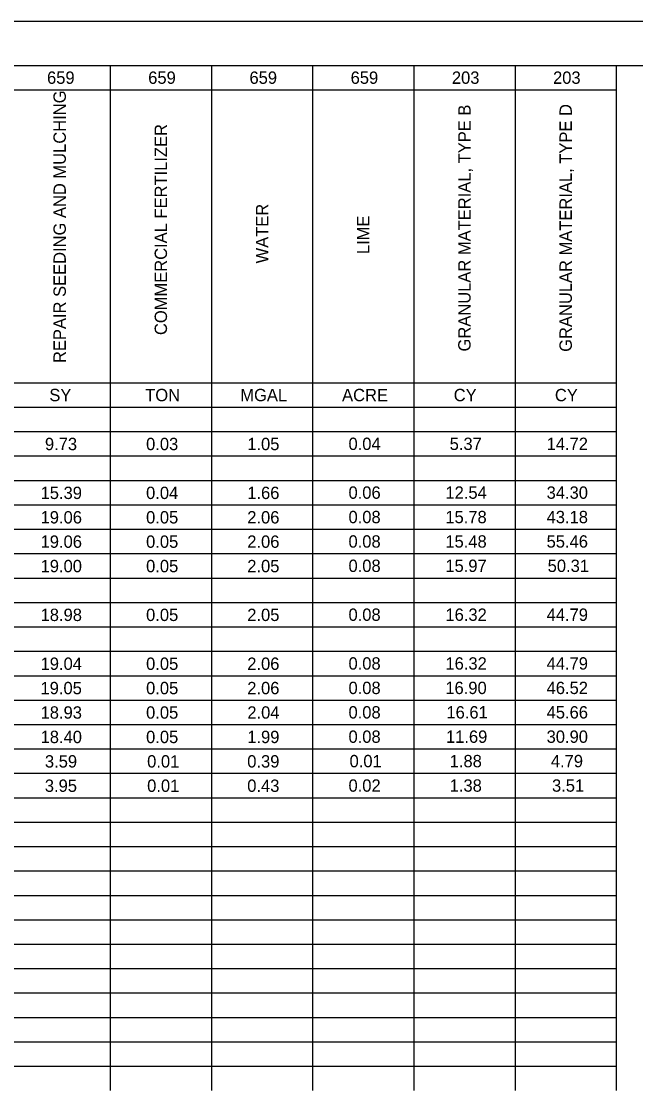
# Model space of a CAD drawing. Extents: x 0 to 34, y 0 to 22.
# Drawn here: x 19.1 to 26.06, y 9.88 to 22 of the extents above; entities that cross this region are included whole.
import ezdxf

# ---------------------------------------------------------------- set-up
doc = ezdxf.new("R2010")
doc.units = 0
for name, color, linetype in [('Default', 7, 'Continuous'), ('SH_Border', 7, 'Continuous'), ('SH_Cut_Line', 7, 'Continuous')]:
    doc.layers.add(name, color=color, linetype=linetype)

msp = doc.modelspace()

# ---------------------------------------------------------------- linework, layer by layer
at = {"layer": 'Default'}
for p, q in [((15.52, 21.5), (25.837, 21.5)), ((20.105, 21.5), (20.105, 21.223)), ((21.252, 21.5), (21.252, 21.223)), ((22.398, 21.5), (22.398, 21.223)), ((23.544, 21.5), (23.544, 21.223)), ((24.691, 21.5), (24.691, 21.223)), ((25.837, 21.5), (25.837, 21.223)), ((15.52, 21.223), (25.837, 21.223)), ((20.105, 21.223), (20.105, 20.947)), ((21.252, 21.223), (21.252, 20.947)), ((22.398, 21.223), (22.398, 20.947)), ((23.544, 21.223), (23.544, 20.947)), ((24.691, 21.223), (24.691, 20.947)), ((25.837, 21.223), (25.837, 20.947)), ((20.105, 20.947), (20.105, 20.67)), ((21.252, 20.947), (21.252, 20.67)), ((22.398, 20.947), (22.398, 20.67)), ((23.544, 20.947), (23.544, 20.67)), ((24.691, 20.947), (24.691, 20.67)), ((25.837, 20.947), (25.837, 20.67)), ((20.105, 20.67), (20.105, 20.116)), ((21.252, 20.67), (21.252, 20.116)), ((22.398, 20.67), (22.398, 20.116)), ((23.544, 20.67), (23.544, 20.116)), ((24.691, 20.67), (24.691, 20.116)), ((25.837, 20.67), (25.837, 20.116)), ((20.105, 20.116), (20.105, 19.84)), ((21.252, 20.116), (21.252, 19.84)), ((22.398, 20.116), (22.398, 19.84)), ((23.544, 20.116), (23.544, 19.84)), ((24.691, 20.116), (24.691, 19.84)), ((25.837, 20.116), (25.837, 19.84)), ((20.105, 19.84), (20.105, 19.563)), ((21.252, 19.84), (21.252, 19.563)), ((22.398, 19.84), (22.398, 19.563)), ((23.544, 19.84), (23.544, 19.563)), ((24.691, 19.84), (24.691, 19.563)), ((25.837, 19.84), (25.837, 19.563)), ((20.105, 19.563), (20.105, 19.286)), ((21.252, 19.563), (21.252, 19.286)), ((22.398, 19.563), (22.398, 19.286)), ((23.544, 19.563), (23.544, 19.286)), ((24.691, 19.563), (24.691, 19.286)), ((25.837, 19.563), (25.837, 19.286)), ((20.105, 19.286), (20.105, 19.01)), ((21.252, 19.286), (21.252, 19.01)), ((22.398, 19.286), (22.398, 19.01)), ((23.544, 19.286), (23.544, 19.01)), ((24.691, 19.286), (24.691, 19.01)), ((25.837, 19.286), (25.837, 19.01)), ((20.105, 19.01), (20.105, 18.733)), ((21.252, 19.01), (21.252, 18.733)), ((22.398, 19.01), (22.398, 18.733)), ((23.544, 19.01), (23.544, 18.733)), ((24.691, 19.01), (24.691, 18.733)), ((25.837, 19.01), (25.837, 18.733)), ((20.105, 18.733), (20.105, 18.456)), ((21.252, 18.733), (21.252, 18.456)), ((22.398, 18.733), (22.398, 18.456)), ((23.544, 18.733), (23.544, 18.456)), ((24.691, 18.733), (24.691, 18.456)), ((25.837, 18.733), (25.837, 18.456)), ((20.105, 18.456), (20.105, 18.18)), ((21.252, 18.456), (21.252, 18.18)), ((22.398, 18.456), (22.398, 18.18)), ((23.544, 18.456), (23.544, 18.18)), ((24.691, 18.456), (24.691, 18.18)), ((25.837, 18.456), (25.837, 18.18)), ((20.105, 18.18), (20.105, 17.903)), ((21.252, 18.18), (21.252, 17.903)), ((22.398, 18.18), (22.398, 17.903)), ((23.544, 18.18), (23.544, 17.903)), ((24.691, 18.18), (24.691, 17.903)), ((25.837, 18.18), (25.837, 17.903)), ((15.52, 17.903), (25.837, 17.903)), ((20.105, 17.903), (20.105, 17.626)), ((21.252, 17.903), (21.252, 17.626)), ((22.398, 17.903), (22.398, 17.626)), ((23.544, 17.903), (23.544, 17.626)), ((24.691, 17.903), (24.691, 17.626)), ((25.837, 17.903), (25.837, 17.626)), ((15.52, 17.626), (25.837, 17.626)), ((20.105, 17.626), (20.105, 17.349)), ((21.252, 17.626), (21.252, 17.349)), ((22.398, 17.626), (22.398, 17.349)), ((23.544, 17.626), (23.544, 17.349)), ((24.691, 17.626), (24.691, 17.349)), ((25.837, 17.626), (25.837, 17.349)), ((15.52, 17.349), (25.837, 17.349)), ((20.105, 17.349), (20.105, 17.073)), ((21.252, 17.349), (21.252, 17.073)), ((22.398, 17.349), (22.398, 17.073)), ((23.544, 17.349), (23.544, 17.073)), ((24.691, 17.349), (24.691, 17.073)), ((25.837, 17.349), (25.837, 17.073)), ((15.52, 17.073), (25.837, 17.073)), ((20.105, 17.073), (20.105, 16.796)), ((21.252, 17.073), (21.252, 16.796)), ((22.398, 17.073), (22.398, 16.796)), ((23.544, 17.073), (23.544, 16.796)), ((24.691, 17.073), (24.691, 16.796)), ((25.837, 17.073), (25.837, 16.796)), ((15.52, 16.796), (25.837, 16.796)), ((20.105, 16.796), (20.105, 16.243)), ((21.252, 16.796), (21.252, 16.243)), ((22.398, 16.796), (22.398, 16.243)), ((23.544, 16.796), (23.544, 16.243)), ((24.691, 16.796), (24.691, 16.243)), ((25.837, 16.796), (25.837, 16.243)), ((15.52, 16.519), (25.837, 16.519)), ((15.52, 16.243), (25.837, 16.243)), ((20.105, 16.243), (20.105, 15.966)), ((21.252, 16.243), (21.252, 15.966)), ((22.398, 16.243), (22.398, 15.966)), ((23.544, 16.243), (23.544, 15.966)), ((24.691, 16.243), (24.691, 15.966)), ((25.837, 16.243), (25.837, 15.966)), ((15.52, 15.966), (25.837, 15.966)), ((20.105, 15.966), (20.105, 15.689)), ((21.252, 15.966), (21.252, 15.689)), ((22.398, 15.966), (22.398, 15.689)), ((23.544, 15.966), (23.544, 15.689)), ((24.691, 15.966), (24.691, 15.689)), ((25.837, 15.966), (25.837, 15.689)), ((15.52, 15.689), (25.837, 15.689)), ((20.105, 15.689), (20.105, 15.412)), ((21.252, 15.689), (21.252, 15.412)), ((22.398, 15.689), (22.398, 15.412)), ((23.544, 15.689), (23.544, 15.412)), ((24.691, 15.689), (24.691, 15.412)), ((25.837, 15.689), (25.837, 15.412)), ((15.52, 15.412), (25.837, 15.412)), ((20.105, 15.412), (20.105, 14.859)), ((21.252, 15.412), (21.252, 14.859)), ((22.398, 15.412), (22.398, 14.859)), ((23.544, 15.412), (23.544, 14.859)), ((24.691, 15.412), (24.691, 14.859)), ((25.837, 15.412), (25.837, 14.859)), ((15.52, 15.136), (25.837, 15.136)), ((15.52, 14.859), (25.837, 14.859)), ((20.105, 14.859), (20.105, 14.582)), ((21.252, 14.859), (21.252, 14.582)), ((22.398, 14.859), (22.398, 14.582)), ((23.544, 14.859), (23.544, 14.582)), ((24.691, 14.859), (24.691, 14.582)), ((25.837, 14.859), (25.837, 14.582)), ((15.52, 14.582), (25.837, 14.582)), ((20.105, 14.582), (20.105, 14.306)), ((21.252, 14.582), (21.252, 14.306)), ((22.398, 14.582), (22.398, 14.306)), ((23.544, 14.582), (23.544, 14.306)), ((24.691, 14.582), (24.691, 14.306)), ((25.837, 14.582), (25.837, 14.306)), ((15.52, 14.306), (25.837, 14.306)), ((20.105, 14.306), (20.105, 14.029)), ((21.252, 14.306), (21.252, 14.029)), ((22.398, 14.306), (22.398, 14.029)), ((23.544, 14.306), (23.544, 14.029)), ((24.691, 14.306), (24.691, 14.029)), ((25.837, 14.306), (25.837, 14.029)), ((15.52, 14.029), (25.837, 14.029)), ((20.105, 14.029), (20.105, 13.199)), ((21.252, 14.029), (21.252, 13.199)), ((22.398, 14.029), (22.398, 13.199)), ((23.544, 14.029), (23.544, 13.199)), ((24.691, 14.029), (24.691, 13.199)), ((25.837, 14.029), (25.837, 13.199)), ((15.52, 13.752), (25.837, 13.752)), ((15.52, 13.476), (25.837, 13.476)), ((15.52, 13.199), (25.837, 13.199)), ((20.105, 13.199), (20.105, 12.922)), ((21.252, 13.199), (21.252, 12.922)), ((22.398, 13.199), (22.398, 12.922)), ((23.544, 13.199), (23.544, 12.922)), ((24.691, 13.199), (24.691, 12.922)), ((25.837, 13.199), (25.837, 12.922)), ((15.52, 12.922), (25.837, 12.922)), ((20.105, 12.922), (20.105, 11.815)), ((21.252, 12.922), (21.252, 11.815)), ((22.398, 12.922), (22.398, 11.815)), ((23.544, 12.922), (23.544, 11.815)), ((24.691, 12.922), (24.691, 11.815)), ((25.837, 12.922), (25.837, 11.815)), ((15.52, 12.645), (25.837, 12.645)), ((15.52, 12.369), (25.837, 12.369)), ((15.52, 12.092), (25.837, 12.092)), ((15.52, 11.815), (25.837, 11.815)), ((20.105, 11.815), (20.105, 11.539)), ((21.252, 11.815), (21.252, 11.539)), ((22.398, 11.815), (22.398, 11.539)), ((23.544, 11.815), (23.544, 11.539)), ((24.691, 11.815), (24.691, 11.539)), ((25.837, 11.815), (25.837, 11.539)), ((15.52, 11.539), (25.837, 11.539)), ((20.105, 11.539), (20.105, 10.432)), ((21.252, 11.539), (21.252, 10.432)), ((22.398, 11.539), (22.398, 10.432)), ((23.544, 11.539), (23.544, 10.432)), ((24.691, 11.539), (24.691, 10.432)), ((25.837, 11.539), (25.837, 10.432)), ((15.52, 11.262), (25.837, 11.262)), ((15.52, 10.985), (25.837, 10.985)), ((15.52, 10.708), (25.837, 10.708)), ((15.52, 10.432), (25.837, 10.432)), ((20.105, 10.432), (20.105, 9.878)), ((21.252, 10.432), (21.252, 9.878)), ((22.398, 10.432), (22.398, 9.878)), ((23.544, 10.432), (23.544, 9.878)), ((24.691, 10.432), (24.691, 9.878)), ((25.837, 10.432), (25.837, 9.878)), ((15.52, 10.155), (25.837, 10.155))]:
    msp.add_line(p, q, dxfattribs=at)
at = {"layer": 'SH_Border'}
msp.add_lwpolyline([(1.5, 21.5), (33.5, 21.5), (33.5, 0.5), (1.5, 0.5)], close=True, dxfattribs=at)
at = {"layer": 'SH_Cut_Line'}
msp.add_lwpolyline([(0, 0), (34, 0), (34, 22), (0, 22)], close=True, dxfattribs=at)

# ---------------------------------------------------------------- texts
at = {"layer": 'Default'}
for s, p in [('659', (19.389, 21.292)), ('659', (20.535, 21.292)), ('659', (21.682, 21.292)), ('659', (22.828, 21.292)), ('203', (23.975, 21.292)), ('203', (25.121, 21.292)), ('SY', (19.415, 17.694)), ('TON', (20.501, 17.694)), ('MGAL', (21.578, 17.694)), ('ACRE', (22.731, 17.694)), ('CY', (23.996, 17.694)), ('CY', (25.142, 17.694)), ('9.73', (19.365, 17.139)), ('0.03', (20.511, 17.139)), ('1.05', (21.657, 17.139)), ('0.04', (22.804, 17.141)), ('5.37', (23.95, 17.141)), ('14.72', (25.048, 17.141)), ('0.06', (22.804, 16.588)), ('12.54', (23.902, 16.588)), ('34.30', (25.048, 16.588)), ('15.39', (19.316, 16.585)), ('0.04', (20.511, 16.585)), ('1.66', (21.657, 16.585)), ('19.06', (19.316, 16.308)), ('0.05', (20.511, 16.308)), ('2.06', (21.657, 16.308)), ('0.08', (22.804, 16.311)), ('15.78', (23.901, 16.311)), ('43.18', (25.048, 16.311)), ('19.06', (19.316, 16.032)), ('0.05', (20.511, 16.032)), ('2.06', (21.657, 16.032)), ('0.08', (22.804, 16.034)), ('15.48', (23.901, 16.034)), ('55.46', (25.048, 16.034)), ('19.00', (19.316, 15.755)), ('0.05', (20.511, 15.755)), ('2.05', (21.657, 15.755)), ('0.08', (22.804, 15.758)), ('15.97', (23.901, 15.758)), ('50.31', (25.06, 15.758)), ('18.98', (19.316, 15.202)), ('0.05', (20.511, 15.202)), ('2.05', (21.657, 15.202)), ('0.08', (22.804, 15.204)), ('16.32', (23.902, 15.204)), ('44.79', (25.048, 15.204)), ('19.04', (19.316, 14.648)), ('0.05', (20.511, 14.648)), ('2.06', (21.657, 14.648)), ('0.08', (22.804, 14.651)), ('16.32', (23.902, 14.651)), ('44.79', (25.048, 14.651)), ('19.05', (19.315, 14.372)), ('0.05', (20.511, 14.372)), ('2.06', (21.657, 14.372)), ('0.08', (22.804, 14.374)), ('16.90', (23.901, 14.374)), ('46.52', (25.048, 14.374)), ('18.93', (19.316, 14.095)), ('0.05', (20.511, 14.095)), ('2.04', (21.658, 14.095)), ('0.08', (22.804, 14.097)), ('16.61', (23.913, 14.097)), ('45.66', (25.048, 14.097)), ('18.40', (19.316, 13.818)), ('0.05', (20.511, 13.818)), ('1.99', (21.657, 13.818)), ('0.08', (22.804, 13.821)), ('11.69', (23.908, 13.821)), ('30.90', (25.048, 13.821)), ('3.59', (19.365, 13.541)), ('0.01', (20.523, 13.541)), ('0.39', (21.657, 13.541)), ('0.01', (22.816, 13.544)), ('1.88', (23.95, 13.544)), ('4.79', (25.096, 13.544)), ('3.95', (19.364, 13.265)), ('0.01', (20.523, 13.265)), ('0.43', (21.657, 13.265)), ('0.02', (22.804, 13.267)), ('1.38', (23.95, 13.267)), ('3.51', (25.109, 13.267))]:
    msp.add_text(s, height=0.14, dxfattribs=at).set_placement(p)
for s, p in [('REPAIR SEEDING AND MULCHING', (19.602, 18.127)), ('GRANULAR MATERIAL, TYPE B', (24.187, 18.258)), ('GRANULAR MATERIAL, TYPE D', (25.334, 18.254)), ('COMMERCIAL FERTILIZER', (20.748, 18.444)), ('WATER', (21.895, 19.256)), ('LIME', (23.041, 19.362))]:
    msp.add_text(s, height=0.14, rotation=90, dxfattribs=at).set_placement(p)

doc.saveas('drawing.dxf')
